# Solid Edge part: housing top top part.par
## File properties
Author: vinurabandara
Template: iso metric part.par
Last saved by: Nimesh.N
Revision: 16
Application: Solid Edge
Density: 1024.000 kg/m^3
Accuracy: 0.990
Username: Nimesh.N
Material: Plastic ABS (extra strong)
Face Style: Black (dull)
Fill Style: Normal Grid
Virtual Style: Normal Grid
Grouping: Non-metals
LibraryName: Materials-GOST
Coef. of Thermal Exp: 9e-05
Thermal Conductivity: 0.2
Specific Heat: 0.0
Modulus of Elasticity: 1378951400.0
Poisson's Ratio: 0.4
Yield Stress: 31026406.5
Ultimate Stress: 0.0
Elongation: 0.0
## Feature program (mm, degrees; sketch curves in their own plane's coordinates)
sketch for "unnamed Protrusion 1" plane through (0, 0, 0) normal (0, -1, 0) x-axis (1, 0, 0)
  line (-580, -115.665) -> (580, -115.665)
  line (580, -115.665) -> (580, 115.665)
  line (580, 115.665) -> (-580, 115.665)
  line (-580, 115.665) -> (-580, -115.665)
  dimension (linear) = 580
  dimension (linear) = 580
extrude "unnamed Protrusion 1" add finite 15 along -normal
sketch for "ExtrudedProtrusion_2" #1 plane through (0, 0, 0) normal (0, -1, 0) x-axis (1, 0, 0)
  line (0, 0) -> (0, 0)
  line (-580, 115.665) -> (580, 115.665)
  line (580, 115.665) -> (580, -115.665)
  line (580, -115.665) -> (-580, -115.665)
  line (-580, -115.665) -> (-580, 115.665)
sketch for "ExtrudedProtrusion_2" #2 plane through (0, 0, 0) normal (0, -1, 0) x-axis (1, 0, 0)
  line (-560, 95.665) -> (560, 95.665)
  line (560, 95.665) -> (560, -95.665)
  line (560, -95.665) -> (-560, -95.665)
  line (-560, -95.665) -> (-560, 95.665)
extrude "ExtrudedProtrusion_2" add finite 40 along +normal
sketch for "unnamed Cutout 1" #1 plane through (-580, -12.5, 0) normal (-1, 0, 0) x-axis (0, 0, 1)
  circle centre (-64.005, -27.5) radius 7.5
sketch for "unnamed Cutout 1" #2 plane through (-580, -12.5, 0) normal (-1, 0, 0) x-axis (0, 0, 1)
  circle centre (65.995, -27.5) radius 7.5
extrude "unnamed Cutout 1" cut through along -normal
sketch for "ExtrudedProtrusion_4" #1 plane through (580, -12.5, 0) normal (1, 0, 0) x-axis (0, 0, 1)
  line (-91.505, 27.5) -> (-36.505, 27.5)
sketch for "ExtrudedProtrusion_4" #2 plane through (580, -12.5, 0) normal (1, 0, 0) x-axis (0, 0, 1)
  line (38.495, 27.5) -> (93.495, 27.5)
extrude "ExtrudedProtrusion_4" add finite 20 along +normal
mirror "unnamed Mirror 1" of "ExtrudedProtrusion_4" about plane through (0, 0, 0) normal (1, 0, 0)
extrude "unnamed Protrusion 2" add finite 20
sketch for "unnamed Cutout 2" #1 plane through (0, 15, 0) normal (0, 1, 0) x-axis (-1, 0, 0)
  line (188, -56.505) -> (38, -56.505)
  line (38, -51.505) -> (38, -56.505)
  line (28, -51.505) -> (38, -51.505)
  line (28, -56.505) -> (28, -51.505)
  line (28, -56.505) -> (-122, -56.505)
  line (-122, -56.505) -> (-122, -71.505)
  line (-122, -71.505) -> (28, -71.505)
  line (28, -76.505) -> (28, -71.505)
  line (38, -76.505) -> (28, -76.505)
  line (38, -71.505) -> (38, -76.505)
  line (38, -71.505) -> (188, -71.505)
  line (188, -71.505) -> (188, -56.505)
sketch for "unnamed Cutout 2" #2 plane through (0, 15, 0) normal (0, 1, 0) x-axis (-1, 0, 0)
  line (188, 73.495) -> (38, 73.495)
  line (38, 78.495) -> (38, 73.495)
  line (28, 78.495) -> (38, 78.495)
  line (28, 73.495) -> (28, 78.495)
  line (28, 73.495) -> (-122, 73.495)
  line (-122, 73.495) -> (-122, 58.495)
  line (-122, 58.495) -> (28, 58.495)
  line (28, 53.495) -> (28, 58.495)
  line (38, 53.495) -> (28, 53.495)
  line (38, 58.495) -> (38, 53.495)
  line (38, 58.495) -> (188, 58.495)
  line (188, 58.495) -> (188, 73.495)
  dimension (linear) = 188
  dimension (linear) = 188
  dimension (linear) = 28
  dimension (linear) = 38
  dimension (linear) = 28
  dimension (linear) = 38
extrude "unnamed Cutout 2" cut through along -normal
fillet "Round_3" radius 7.5
fillet "Round_4" radius 2
sketch for "ExtrudedProtrusion_6" plane through (0, -12.5, -115.665) normal (0, 0, -1) x-axis (-1, 0, 0)
  line (8.7576, 27.5) -> (19.2111, 27.5)
  line (19.2111, 27.5) -> (19.2111, 21.7815)
  line (19.2111, 21.7815) -> (8.7576, 21.7815)
  line (8.7576, 21.7815) -> (8.7576, 27.5)
extrude "ExtrudedProtrusion_6" add finite 10 along +normal
sketch for "ExtrudedProtrusion_7" plane through (0, -12.5, -115.665) normal (0, 0, -1) x-axis (-1, 0, 0)
  line (-580, -27.5) -> (580, -27.5)
  line (580, -27.5) -> (580, -17.5)
  line (580, -17.5) -> (-580, -17.5)
  line (-580, -17.5) -> (-580, -27.5)
extrude "ExtrudedProtrusion_7" add finite 30 along +normal
fillet "Round_5" radius 20
sketch for "unnamed Cutout 3" plane through (0, -30, -130.665) normal (0, 1, 0) x-axis (-1, 0, 0)
  circle centre (-480, 0) radius 7.5
extrude "unnamed Cutout 3" cut through along -normal
pattern "unnamed Pattern 1" of "unnamed Cutout 3"
pattern "unnamed Pattern 2"
mirror "unnamed Mirror 2" of "ExtrudedProtrusion_7" about plane through (0, 0, 0) normal (0, 0, 1)
extrude "unnamed Protrusion 3" add finite 30
mirror "unnamed Mirror 3" of "unnamed Pattern 2", "unnamed Cutout 3", "Round_5"
pattern "unnamed Pattern 3"
fillet "Round_7" radius 5
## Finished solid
Body 1: solid body, 94 faces, 259 edges, 158 vertices.
  Faces by surface: cylinder 47, plane 47
  Edges by curve: line 169, circle 86, ellipse 4
Bounding box of the edges (mm): 1200.000 x 55.000 x 291.330, from (-600, -40, -145.665) to (600, 15, 145.665).
Cylindrical faces by radius (mm): R2 x16, R5 x5, R7.5 x18, R20 x4, R27.5 x4
Planar faces by outward normal: +x 11, +y 3, +z 9, -x 11, -y 3, -z 10
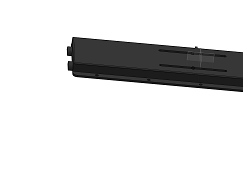
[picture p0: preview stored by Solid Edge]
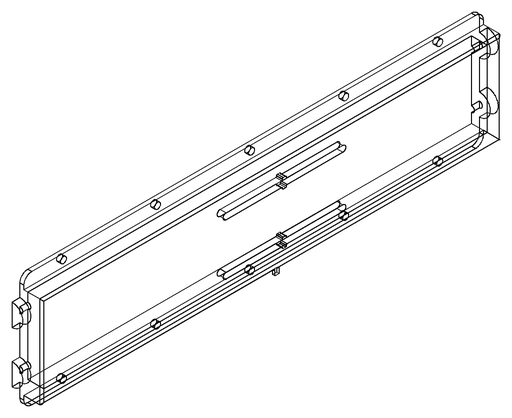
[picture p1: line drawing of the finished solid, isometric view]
